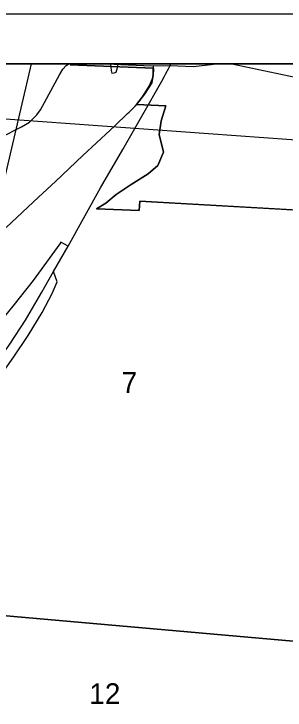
# Model space of a CAD drawing. Extents: x -209 to 4852, y 0 to 905.
# Drawn here: x 525.56 to 536.44, y 312.57 to 340.56 of the extents above; entities that cross this region are included whole.
import ezdxf

# ---------------------------------------------------------------- set-up
doc = ezdxf.new("R2010")
doc.units = 0
for name, color, linetype in [('Default', 7, 'Continuous'), ('GM_X_Airport_Location_Class_2', 7, 'Continuous'), ('GM_X_County_Subdivision_Text', 7, 'Continuous'), ('GM_X_Major_Lake', 7, 'Continuous'), ('GM_X_Minor_River', 7, 'Continuous'), ('GM_X_Rail_Line', 7, 'Continuous'), ('GM_X_Rail_Line_Text', 7, 'Continuous'), ('GM_X_Township_Road_Text', 7, 'Continuous'), ('GM_X_US_Location', 7, 'Continuous'), ('GM_X_US_Route', 7, 'Continuous'), ('SH_Data', 7, 'Continuous')]:
    doc.layers.add(name, color=color, linetype=linetype)

msp = doc.modelspace()

# ---------------------------------------------------------------- linework, layer by layer
at = {"layer": 'Default'}
msp.add_lwpolyline([(571.768, 202.559), (571.768, 338.559), (435.768, 338.559), (435.768, 202.559)], close=True, dxfattribs=at)
at = {"layer": 'GM_X_Airport_Location_Class_2'}
msp.add_line((529.239, 338.559), (529.569, 338.538), dxfattribs=at)
for points in [[(523.657, 334.828), (524.35, 335.228), (525.014, 335.595), (525.857, 336.016), (526.185, 336.212), (526.291, 336.318), (526.472, 336.504), (526.624, 336.708), (526.788, 336.995), (527.387, 338.109), (527.521, 338.334), (527.658, 338.481), (527.765, 338.559)], [(529.569, 338.538), (529.854, 338.52), (530.777, 338.482)], [(530.32, 336.747), (530.421, 336.846), (530.609, 337.059), (530.814, 337.37), (530.986, 337.656), (531.084, 337.869), (531.154, 338.021), (531.178, 338.291), (531.166, 338.467)], [(530.777, 338.482), (531.166, 338.467), (531.825, 338.483), (532.752, 338.447), (532.991, 338.473)], [(532.991, 338.473), (533.476, 338.527), (533.666, 338.559)], [(530.179, 336.608), (530.32, 336.747)], [(529.606, 336.06), (530.119, 336.55), (530.179, 336.608)], [(525.247, 331.978), (526.54, 333.187), (527.222, 333.826), (528.331, 334.873), (529.417, 335.885), (529.606, 336.06)]]:
    msp.add_lwpolyline(points, dxfattribs=at)
at = {"layer": 'GM_X_County_Subdivision_Text'}
msp.add_lwpolyline([(523.682, 324.002), (523.789, 324.191), (523.943, 324.458), (524.267, 325.01), (524.867, 325.822), (525.548, 326.771), (526.123, 327.628), (526.695, 328.548), (527.097, 329.318), (527.296, 329.788), (527.142, 330.203)], dxfattribs=at)
at = {"layer": 'GM_X_Major_Lake'}
msp.add_lwpolyline([(529.441, 338.559), (529.445, 338.417), (529.465, 338.28), (529.493, 338.173), (529.584, 338.186), (529.661, 338.223), (529.693, 338.314), (529.726, 338.45), (529.743, 338.559)], dxfattribs=at)
at = {"layer": 'GM_X_Minor_River'}
for points in [[(533.673, 338.559), (521.288, 338.559), (521.14, 336.64), (541.147, 335.189), (541.389, 336.783), (539.868, 337.25), (537.101, 337.946), (534.302, 338.536)], [(521.14, 336.64), (541.147, 335.189), (539.188, 315.131), (519.33, 316.881)], [(519.33, 316.881), (539.188, 315.131), (539.664, 315.099), (539.314, 310.159), (518.834, 311.823)]]:
    msp.add_lwpolyline(points, close=True, dxfattribs=at)
at = {"layer": 'GM_X_Rail_Line'}
msp.add_lwpolyline([(527.741, 331.222), (527.441, 331.388), (527.395, 331.321), (526.326, 329.836), (525.513, 328.815), (525.166, 328.38), (524.857, 328.044), (524.788, 327.981), (524.736, 327.94), (524.733, 327.936), (524.673, 327.902), (524.61, 327.882), (524.562, 327.888), (524.534, 327.897), (524.458, 327.942), (524.431, 327.964), (524.402, 328), (524.389, 328.035), (524.385, 328.052), (524.175, 328.106)], dxfattribs=at)
at = {"layer": 'GM_X_Rail_Line_Text'}
for points in [[(531.604, 338.058), (531.643, 338.132), (531.785, 338.406)], [(531.785, 338.406), (531.825, 338.483), (531.864, 338.559)], [(526.801, 329.585), (527.142, 330.203), (527.741, 331.222), (529.033, 333.561), (529.93, 335.114), (530.731, 336.516), (531.501, 337.861), (531.604, 338.058)], [(518.755, 320.948), (519.619, 321.506), (520.398, 322.048), (521.312, 322.744), (522.305, 323.661), (523.044, 324.37), (523.636, 325.016), (524.206, 325.699), (524.725, 326.342), (525.397, 327.287), (526.019, 328.252), (526.683, 329.371), (526.801, 329.585)]]:
    msp.add_lwpolyline(points, dxfattribs=at)
at = {"layer": 'GM_X_US_Location'}
for points in [[(539.07, 332.547), (530.617, 333.026), (530.586, 332.658), (528.869, 332.719), (529.244, 332.955), (529.658, 333.293), (530.264, 333.707), (530.954, 334.131), (531.338, 334.466), (531.56, 334.996), (531.392, 335.709), (531.468, 336.254), (531.652, 336.867), (530.476, 336.919), (530.797, 337.335), (531.094, 337.787), (531.154, 338.12), (531.153, 338.383), (527.813, 338.508), (527.841, 338.559), (515.21, 338.559)], [(548.141, 338.559), (527.841, 338.559), (527.813, 338.508), (531.153, 338.383), (531.154, 338.12), (531.094, 337.787), (530.797, 337.335), (530.476, 336.919), (531.652, 336.867), (531.468, 336.254), (531.392, 335.709), (531.56, 334.996), (531.338, 334.466), (530.954, 334.131), (530.264, 333.707), (529.658, 333.293), (529.244, 332.955), (528.869, 332.719), (530.586, 332.658), (530.617, 333.026), (540.772, 332.45)], [(548.141, 338.559), (527.841, 338.559), (527.813, 338.508), (531.153, 338.383), (531.154, 338.12), (531.094, 337.787), (530.797, 337.335), (530.476, 336.919), (531.652, 336.867), (531.468, 336.254), (531.392, 335.709), (531.56, 334.996), (531.338, 334.466), (530.954, 334.131), (530.264, 333.707), (529.658, 333.293), (529.244, 332.955), (528.869, 332.719), (530.586, 332.658), (530.617, 333.026), (540.772, 332.45)]]:
    msp.add_lwpolyline(points, dxfattribs=at)
at = {"layer": 'GM_X_US_Route'}
msp.add_lwpolyline([(519.918, 312.42), (519.993, 313.232), (520.083, 313.92), (520.229, 314.667), (520.941, 317.713), (521.152, 318.616), (521.368, 319.575), (521.543, 320.217), (521.684, 320.724), (522.13, 321.913), (522.637, 323.418), (523.144, 325.245), (523.51, 326.81), (523.727, 327.727), (524.195, 329.727), (525, 333.152), (526.259, 338.559)], dxfattribs=at)
at = {"layer": 'SH_Data'}
for p, q in [((433.768, 340.559), (573.768, 340.559)), ((435.768, 338.559), (571.768, 338.559))]:
    msp.add_line(p, q, dxfattribs=at)

# ---------------------------------------------------------------- texts
at = {"layer": 'GM_X_Township_Road_Text'}
for s, height, p in [('7', 0.837, (529.886, 325.322)), ('12', 0.8371, (528.586, 312.81))]:
    msp.add_text(s, height=height, rotation=0, dxfattribs=at).set_placement(p)

doc.saveas('drawing.dxf')
